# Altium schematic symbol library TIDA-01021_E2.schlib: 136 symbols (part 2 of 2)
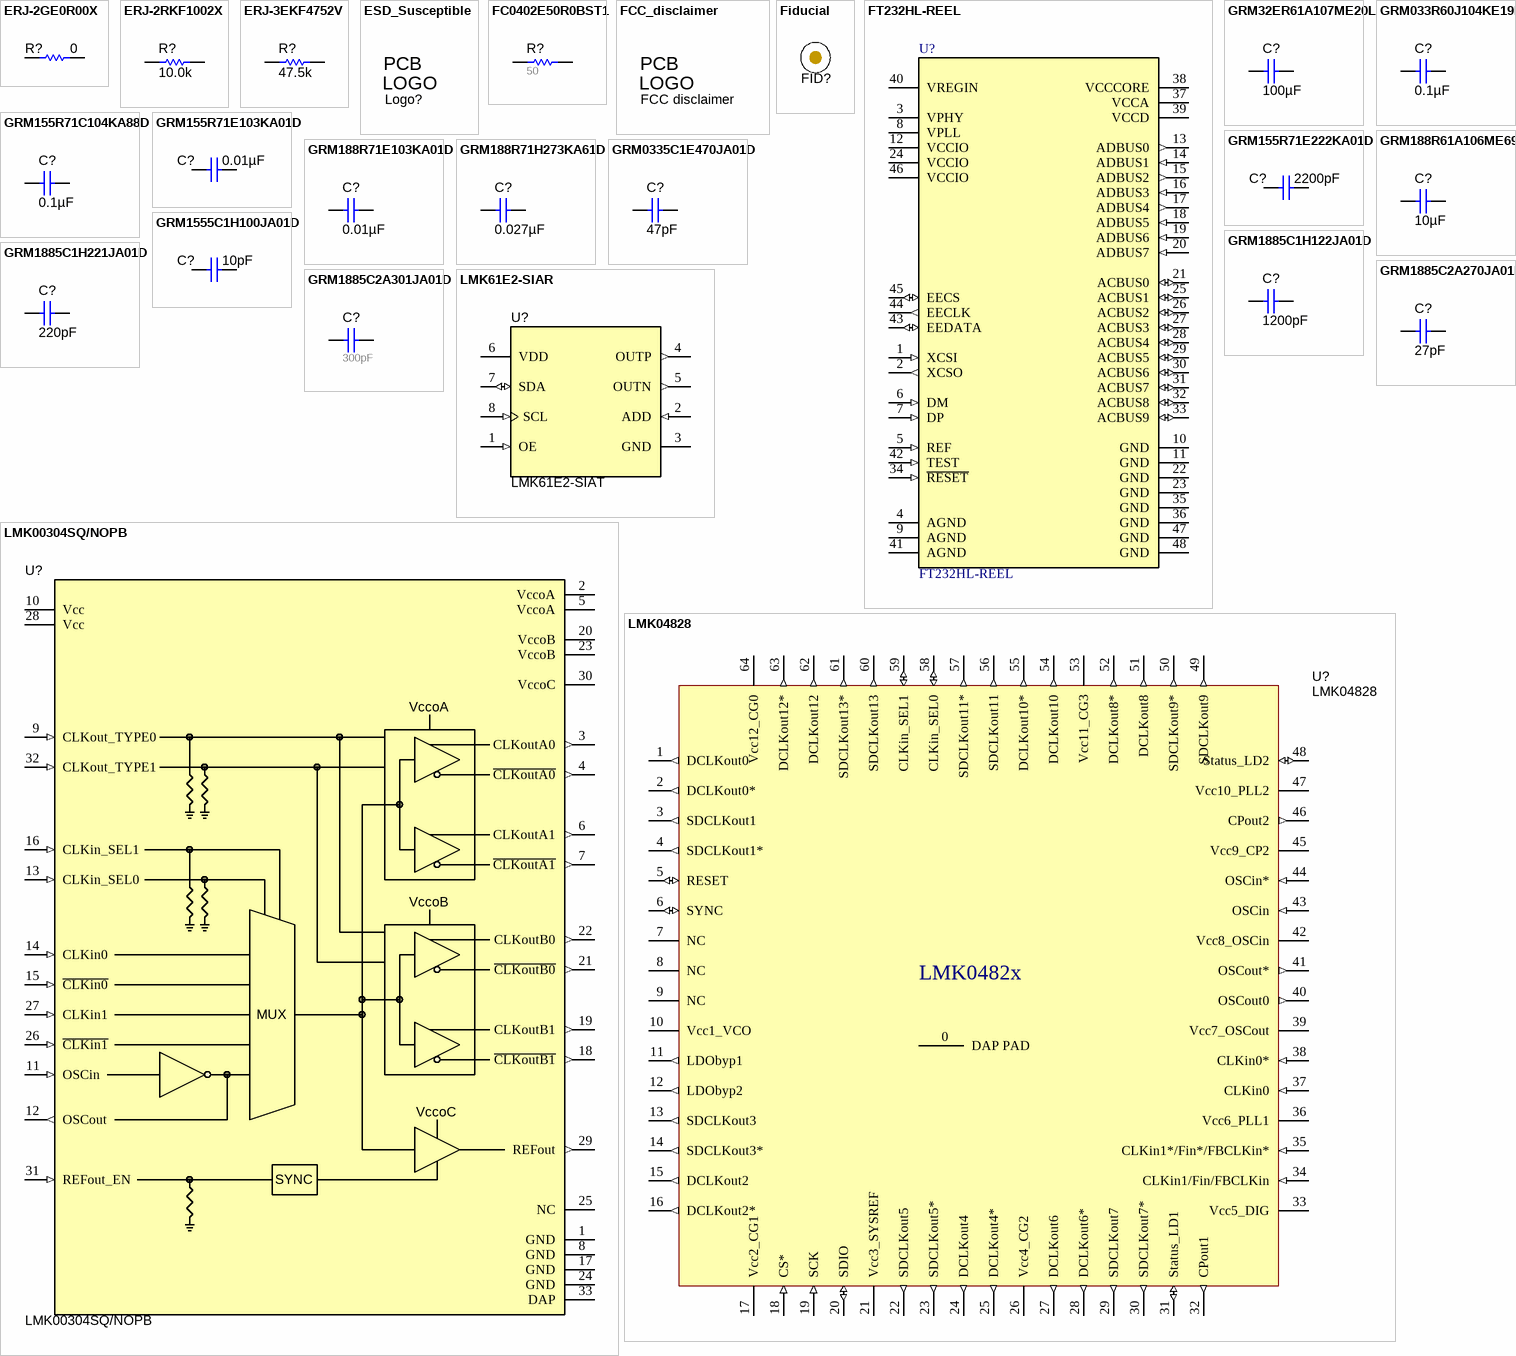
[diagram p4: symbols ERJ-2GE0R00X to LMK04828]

## LMK04828
designator U?
Manufacturer: Texas Instruments; PartNumber: LMK04828BISQ
footprint LLP64(NS_SQA64A)_HYBRID
footprint NKD0064A (QFN, 64-Leads, Body 9x9mm, Pitch 0.5mm)
pins: 0 DAP PAD (power) "DAP", 1 DCLKout0 (out) "CG0", 2 DCLKout0* (out) "CG0", 3 SDCLKout1 (out) "CG0", 4 SDCLKout1* (out) "CG0", 5 RESET (io), 6 SYNC (io), 7 NC, 8 NC, 9 NC, 10 Vcc1_VCO (power) "VCC_VCO_LDO", 11 LDObyp1 (out), 12 LDObyp2 (out), 13 SDCLKout3 (out) "CG1", 14 SDCLKout3* (out) "CG1", 15 DCLKout2 (out) "CG1", 16 DCLKout2* (out) "CG1", 17 Vcc2_CG1 (power) "VCC_CG1", 18 CS* (in), 19 SCK (in) "CG2", 20 SDIO (io) "CG2", 21 Vcc3_SYSREF (power) "CG2", 22 SDCLKout5 (out) "CG2", 23 SDCLKout5* (out), 24 DCLKout4 (out) "VCC_Digital", 25 DCLKout4* (out), 26 Vcc4_CG2 (power), 27 DCLKout6 (out) "Status", 28 DCLKout6* (out), 29 SDCLKout7 (out), 30 SDCLKout7* (out), 31 Status_LD1 (io), 32 CPout1 (out), 33 Vcc5_DIG (power) "Status", 34 CLKin1/Fin/FBCLKin (in), 35 CLKin1*/Fin*/FBCLKin* (in) "VCC_CP1", 36 Vcc6_PLL1 (power), 37 CLKin0 (in), 38 CLKin0* (in) "VCC_OSCin", 39 Vcc7_OSCout (power), 40 OSCout0 (out), 41 OSCout* (out) "OSCout", 42 Vcc8_OSCin (power), 43 OSCin (in) "VCC_DIV", 44 OSCin* (in) "uWire", 45 Vcc9_CP2 (power) "Vcc_CP2", 46 CPout2 (out) "uWire", 47 Vcc10_PLL2 (power) "Vcc_PLL2", 48 Status_LD2 (io) "CG3", 49 SDCLKout9 (out) "CG3", 50 SDCLKout9* (out) "CG3", 51 DCLKout8 (out) "CG3", 52 DCLKout8* (out) "VCC_CG4", 53 Vcc11_CG3 (power) "CG4", 54 DCLKout10 (out) "CG4", 55 DCLKout10* (out) "CG4", 56 SDCLKout11 (out) "CG4", 57 SDCLKout11* (out) "VCC_CG5", 58 CLKin_SEL0 (io) "CG5", 59 CLKin_SEL1 (io) "CG5", 60 SDCLKout13 (out) "CG5", 61 SDCLKout13* (out) "CG5", 62 DCLKout12 (out) "Status", 63 DCLKout12* (out), 64 Vcc12_CG0 (power)

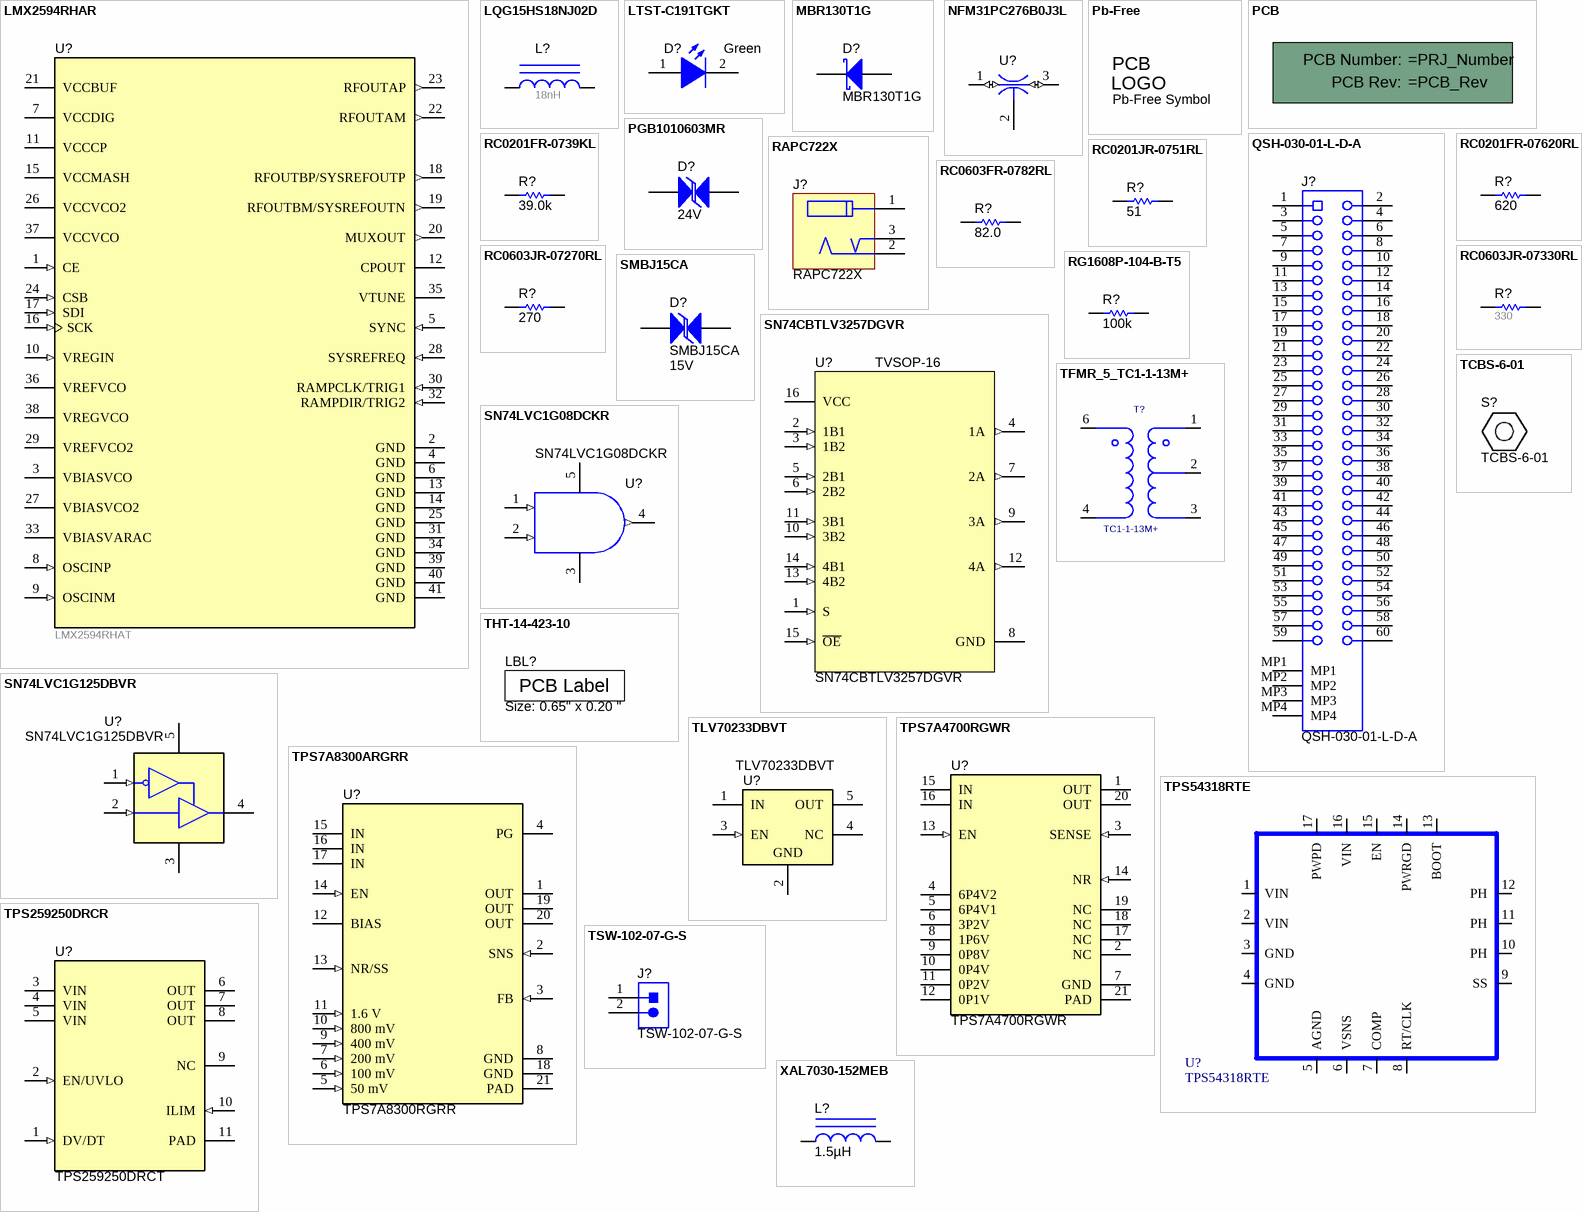
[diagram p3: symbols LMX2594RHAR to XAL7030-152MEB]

## LMX2594RHAR
designator U?, comment LMX2594RHAT
High Performance, Wideband PLLatinum RF Synthesizer, RHA0040A (VQFN-40); Manufacturer: Texas Instruments; SymbolCreator: Altium; SizeArea_mm2: 36; SizeAreaWB_mm2: 64; SizeX_mm: 6; SizeZ_mm: 1; CompType: IC; U/M: EA
footprint RHA0040A (QFN, 40-Leads, Body 6x6mm, Pitch 0.5mm, Thermal Pad 4.6x4.6mm, TI Recommended)
footprint RHA0040A_NV
footprint RHA0040C
pins: 1 CE (in), 2 GND (power), 3 VBIASVCO, 4 GND (power), 5 SYNC (in), 6 GND (power), 7 VCCDIG (power), 8 OSCINP (in), 9 OSCINM (in), 10 VREGIN (in), 11 VCCCP (power), 12 CPOUT, 13 GND (power), 14 GND (power), 15 VCCMASH (power), 16 SCK (in), 17 SDI (in), 18 RFOUTBP/SYSREFOUTP (out), 19 RFOUTBM/SYSREFOUTN (out), 20 MUXOUT (out), 21 VCCBUF (power), 22 RFOUTAM (out), 23 RFOUTAP (out), 24 CSB (in), 25 GND (power), 26 VCCVCO2 (power), 27 VBIASVCO2, 28 SYSREFREQ (in), 29 VREFVCO2, 30 RAMPCLK/TRIG1 (in), 31 GND (power), 32 RAMPDIR/TRIG2 (in), 33 VBIASVARAC, 34 GND (power), 35 VTUNE, 36 VREFVCO, 37 VCCVCO (power), 38 VREGVCO, 39 GND (power), 40 GND (power), 41 GND (power)

## LQG15HS18NJ02D
designator L?  ValueDisplayed: 18nH  (hidden comment: LQG15HS18NJ02D)
Inductor, Multilayer, Air Core, 18 nH, 0.3 A, 0.36 ohm, SMD; Manufacturer: MuRata; Value: 18nH; Ind_H: 18.0E-9; Imax_A: 0.3; Irms: 0.3A @ C rise; Isat: 0.3A @ % inductance drop; DCR_ohm: 0.36; Value2: 0.3A; AEC Category: Q200
signal-integrity model Inductor
simulation model Inductor
footprint IND_LQG15H
pins: 1, 2

## LTST-C191TGKT
designator D?  value Green  (hidden comment: LTST-C191TGKT)
LED, Green, SMD; Manufacturer: Lite-On; Type: InGaN; Vf_V: 3.2; Value2: 3.2V; Io_A: 0.02; Value1: W; U/M: EA
signal-integrity model Diode
footprint LTST-C191_Green
pins: 1 A, 2 K

## MBR130T1G
designator D?
Diode, Schottky, 30 V, 1 A, SOD-123; Manufacturer: ON Semiconductor; U/M: EA; Vf_V: 0.47; Value: 30V; Value1: 1A; Value2: 0.47V; Io_A: 1; Vr_V: 30; TJmax_C: 125; RJC_CperW: 108; SizeAreaWB_mm2: 13.095; SizeArea_mm2: 6.545; SizeX_mm: 3.85; SizeY_mm: 1.7; SizeZ_mm: 1.35; AEC Category: Q101
signal-integrity model Diode
simulation model mbr130prl
footprint SOD-123
pins: 1 K, 2 A

## NFM31PC276B0J3L
designator U?  (value not drawn)
FILTER LC HIGH FREQ 27uF 1206; Manufacturer: MuRata; SymbolCreator: Altium
footprint Murata_NFM31P
pins: 1 (io), 2 (power), 3 (io)

## Pb-Free
designator Logo?, comment Pb-Free Symbol  (no BOM)
SymbolCreator: a0412235
footprint Pb-Free_Overlay_Medium
footprint Pb-Free_Overlay_Small

## PCB
designator !PCB?, comment Printed Circuit Board  (value not drawn)  (mechanical)
Manufacturer: Any; SymbolCreator: a0412235; CompType: PCB
1 alternate drawing of the same symbol

## PGB1010603MR
designator D?  value 24V  (hidden comment: PGB1010603MR)
PulseGuard ESD Suppressor, 24VDC, SMT; Manufacturer: Littelfuse
footprint PGB1_0603
pins: 1, 2

## QSH-030-01-L-D-A
designator J?
Receptacle, 0.5 mm, 30x2, Gold, TH; Manufacturer: Samtec; SymbolCreator: Altium; Pitch_mm: 0.5; Gender: Female; Shrouded: N; Row_Count: 2; RowSpacing_mm: 5.73
footprint Samtec_QSH-030-01-X-D-A
pins: 1, 2, 3, 4, 5, 6, 7, 8, 9, 10, 11, 12, 13, 14, 15, 16, 17, 18, 19, 20, 21, 22, 23, 24, 25, 26, 27, 28, 29, 30, 31, 32, 33, 34, 35, 36, 37, 38, 39, 40, 41, 42, 43, 44, 45, 46, 47, 48, 49, 50, 51, 52, 53, 54, 55, 56, 57, 58, 59, 60, MP1, MP2, MP3, MP4

## RAPC722X
designator J?
Power Jack, mini, 2.1mm OD, R/A, TH; Manufacturer: Switchcraft; SymbolCreator: a0799628
footprint CONN_RAPC722X
pins: 1, 2, 3

## RC0201FR-0739KL
designator R?  ValueDisplayed: 39.0k  (hidden comment: RC0201FR-0739KL)
RES, 39.0 k, 1%, 0.05 W, 0201; Manufacturer: Yageo America; CompType: Resistor; Value: 39.0k; Res_ohm: 39000; Value_Code: 39k0; Tolerance_%: 1; Power_W: 0.05; Value2: 0.05W; VDC_V: 25; TempCo: 200 ppm/C; SizeArea_mm2: 0.18; SizeX_mm: 0.6; SizeY_mm: 0.3; SizeZ_mm: 0.26; U/M: EA; AEC Category: Q200; AEC Qualified: N
signal-integrity model Resistor
simulation model Resistor
footprint 0201
footprint 0201M
footprint 0201L
footprint 0201_Silk
pins: 1, 2

## RC0201FR-07620RL
designator R?  ValueDisplayed: 620  (hidden comment: RC0201FR-07620RL)
RES, 620, 1%, 0.05 W, 0201; Manufacturer: Yageo America; CompType: Resistor; Value: 620; Value_Code: 620R; Tolerance_%: 1; Power_W: 0.05; Value2: 0.05W; VDC_V: 25; TempCo: 200 ppm/C; SizeArea_mm2: 0.18; SizeX_mm: 0.6; SizeY_mm: 0.3; SizeZ_mm: 0.26; U/M: EA; AEC Category: Q200; AEC Qualified: N
signal-integrity model Resistor
simulation model Resistor
footprint 0201
footprint 0201M
footprint 0201L
footprint 0201_Silk
pins: 1, 2

## RC0201JR-0751RL
designator R?  ValueDisplayed: 51  (hidden comment: RC0201JR-0751RL)
RES, 51, 5%, 0.05 W, 0201; Manufacturer: Yageo America; CompType: Resistor; Value: 51; Value_Code: 51R0; Tolerance_%: 5; Power_W: 0.05; Value2: 0.05W; VDC_V: 25; TempCo: 200 ppm/C; SizeArea_mm2: 0.18; SizeX_mm: 0.6; SizeY_mm: 0.3; SizeZ_mm: 0.26; EIA_Code: E24; U/M: EA; AEC Category: Q200; AEC Qualified: N
signal-integrity model Resistor
simulation model Resistor
footprint 0201
footprint 0201M
footprint 0201L
footprint 0201_Silk
pins: 1, 2

## RC0603FR-0782RL
designator R?  ValueDisplayed: 82.0  (hidden comment: RC0603FR-0782RL)
RES, 82.0, 1%, 0.1 W, 0603; Manufacturer: Yageo America; CompType: Resistor; Value: 82.0; Res_ohm: 82; Value_Code: 82R0; Tolerance_%: 1; Power_W: 0.1; Value2: 0.1W; VDC_V: 150; TempCo: 200 ppm/C; SizeArea_mm2: 1.28; SizeX_mm: 1.6; SizeY_mm: 0.8; U/M: EA; AEC Category: Q200
signal-integrity model Resistor
simulation model Resistor
footprint 0603
footprint 0603M
footprint 0603L
footprint 0603_HV
footprint 0603S
pins: 1, 2

## RC0603JR-07270RL
designator R?  ValueDisplayed: 270  (hidden comment: RC0603JR-07270RL)
RES, 270, 5%, 0.1 W, 0603; Manufacturer: Yageo America; CompType: Resistor; Tolerance_%: 5; VDC_V: 50; Power_W: 0.1; Value: 270; U/M: EA; Value_Code: 270R; Value2: 0.1W; TempCo: 100 ppm/C; EIA_Code: E24; SizeArea_mm2: 1.28; SizeX_mm: 1.6; SizeY_mm: 0.8; SizeZ_mm: 1; AEC Category: Q200
signal-integrity model Resistor
simulation model Resistor
footprint 0603
footprint 0603M
footprint 0603L
footprint 0603_HV
footprint 0603S
pins: 1, 2

## RC0603JR-07330RL
designator R?  value 330  (hidden comment: RC0603JR-07330RL)
RES, 330 ohm, 5%, 0.1W, 0603; Manufacturer: Yageo America; CompType: Resistor; Tolerance_%: 5; VDC_V: 50; Power_W: 0.1; U/M: EA; Value_Code: 330R; EIA_Code: E24
signal-integrity model Resistor
simulation model Resistor
footprint 0603
footprint 0603M
footprint 0603L
footprint 0603_HV
pins: 1, 2

## RG1608P-104-B-T5
designator R?  ValueDisplayed: 100k  (hidden comment: RG1608P-104-B-T5)
RES, 100 k, 0.1%, 0.1 W, 0603; Manufacturer: Susumu Co Ltd; CompType: Resistor; Value: 100k; Res_ohm: 100000; Tolerance_%: 0.1; Value2: 0.1W; VDC_V: 75; TempCo: 25 ppm/C; SizeArea_mm2: 1.28; SizeX_mm: 1.6; SizeY_mm: 0.8; SizeZ_mm: 1; EIA_Code: E192; U/M: EA; AEC Category: Q200
signal-integrity model Resistor
simulation model Resistor
footprint 0603
footprint 0603M
footprint 0603L
footprint 0603_HV
footprint 0603S
pins: 1, 2

## SMBJ15CA
designator D?  value 15V
Diode, TVS, Bi, 15 V, 24.4 Vc, SMB; Manufacturer: Fairchild Semiconductor; U/M: EA; Vr_V: 15; Value1: W; AEC Category: Q101
footprint SMB-Bi
pins: 1, 2

## SN74CBTLV3257DGVR
designator U?  PackageDescription: TVSOP-16
Low-Voltage 4-Bit 1-Of-2 FET Multiplexer/Demultiplexer, DGV0016A (TVSOP-16); Manufacturer: Texas Instruments; SymbolCreator: Altium; SizeArea_mm2: 40.96; SizeAreaWB_mm2: 70.56; SizeX_mm: 6.4; SizeZ_mm: 1.2; CompType: IC; U/M: EA
footprint DGV0016A_N
footprint DGV0016A_M
footprint DGV0016A_L
pins: 1 S (in), 2 1B1 (in), 3 1B2 (in), 4 1A (out), 5 2B1 (in), 6 2B2 (in), 7 2A (out), 8 GND (power), 9 3A (out), 10 3B2 (in), 11 3B1 (in), 12 4A (out), 13 4B2 (in), 14 4B1 (in), 15 ~{OE} (in), 16 VCC (power)

## SN74LVC1G08DCKR
designator U?
Single 2-Input Positive-AND Gate, DCK0005A (SOT-5); Alternate PartNumber: SN74LVC1G08DCKT; Manufacturer: Texas Instruments; CompType: IC; SizeArea_mm2: 4.2; SizeAreaWB_mm2: 9.3; SizeX_mm: 2.1; SizeY_mm: 2; SizeZ_mm: 1.1; U/M: EA
footprint DCK0005A_N
footprint DCK0005A_M
footprint DCK0005A_L
pins: 1 A (in), 2 B (in), 3 V- (power), 4 Y (out), 5 V+ (power)

## SN74LVC1G125DBVR
designator U?
Single Bus Buffer Gate With 3-State Outputs, DBV0005A (SOT-5); Alternate PartNumber: SN74LVC1G125DBVT; Manufacturer: Texas Instruments; SymbolCreator: Altium; SizeArea_mm2: 8.12; SizeAreaWB_mm2: 14.82; SizeX_mm: 2.8; SizeY_mm: 2.9; SizeZ_mm: 1.45; CompType: IC; U/M: EA
footprint DBV0005A_N
footprint DBV0005A_M
footprint DBV0005A_L
pins: 1 ~{OE} (in), 2 A (in), 3 GND (power), 4 Y (hiz), 5 VCC (power)

## TCBS-6-01
designator S?
HEX STANDOFF SPACER, 9.53 mm; Manufacturer: Richco Plastics; SymbolCreator: a0412235
footprint TCBS-6-01

## TFMR_5_TC1-1-13M+
designator T?, comment TC1-1-13M+
Mfr_Name: Mini-Circuits; Mfr-_Part_Number: TC1-1-13MA+
footprint TFMR_5_150x150_50
footprint TFMR_5_150x150_50
pins: 1 secondary_dot, 2 secondary_ct, 3 secondary, 4 primary, 6 primary_dot

## THT-14-423-10
designator LBL?, comment Size: 0.65" x 0.20 "
Thermal Transfer Printable Labels, 0.650" W x 0.200" H - 10,000 per roll; Manufacturer: Brady; PartNumber: THT-14-423-10; SymbolCreator: a0412235; CompType: Label
footprint Label_650x200

## TLV70233DBVT
designator U?
Single Output LDO, 300 mA, Fixed 3.3 V Output, 2 to 5.5 V Input, with Low IQ, 5-pin SOT-23 (DBV), -40 to 125 degC, Green (RoHS & no Sb/Br); Manufacturer: Texas Instruments; Alternate PartNumber: Equivalent; Accuracy(%): 2; Fixed Output Options(V): 3.3; Iout(Max)(A): 0.3; Iq(Typ)(mA): 0.03; SubFamily: Single Channel LDO; Vdo(Typ)(mV): 220; Vin(Max)(V): 5.5
footprint DBV0005A_N (SOT23, 5-Leads, Body 2.9x1.6mm, Pitch 0.95mm, IPC Medium Density)
footprint DBV0005A_L (SOT23, 5-Leads, Body 2.9x1.6mm, Pitch 0.95mm, IPC High Density)
footprint DBV0005A_M (SOT23, 5-Leads, Body 2.9x1.6mm, Pitch 0.95mm, IPC Low Density)
pins: 1 IN (power) "Input supply voltage", 2 GND (power) "Ground", 3 EN (in) "Enable input", 4 NC "No connected", 5 OUT (power) "Regulated output voltage"

## TPS7A4700RGWR
designator U?
36-V, 1-A, 4.17-μVRMS, RF LDO Voltage Regulator, RGW0020A (VQFN-20); Alternate PartNumber: TPS7A4700RGWT; Manufacturer: Texas Instruments; SymbolCreator: a0412235; SizeArea_mm2: 25; SizeAreaWB_mm2: 49; SizeX_mm: 5; SizeZ_mm: 1; CompType: IC; U/M: EA
footprint RGW0020A
pins: 1 OUT (power), 2 NC, 3 SENSE (in), 4 6P4V2, 5 6P4V1, 6 3P2V, 7 GND (power), 8 1P6V, 9 0P8V, 10 0P4V, 11 0P2V, 12 0P1V, 13 EN (in), 14 NR (in), 15 IN (power), 16 IN (power), 17 NC, 18 NC, 19 NC, 20 OUT (power), 21 PAD

## TPS7A8300ARGRR
designator U?, comment TPS7A8300RGRR
2-A, 6-uVRMS, RF, LDO Voltage Regulator, RGR0020A (VQFN-20); Manufacturer: Texas Instruments; SymbolCreator: a0411947; SizeArea_mm2: 12.25; SizeAreaWB_mm2: 20.25; SizeX_mm: 3.5; SizeZ_mm: 1; CompType: IC; U/M: EA
footprint RGR0020A
footprint RGR0020A_NV
pins: 1 OUT (power), 2 SNS (in), 3 FB (in), 4 PG (oc), 5 50 mV (in), 6 100 mV (in), 7 200 mV (in), 8 GND (power), 9 400 mV (in), 10 800 mV (in), 11 1.6 V (in), 12 BIAS (power), 13 NR/SS (in), 14 EN (in), 15 IN (power), 16 IN (power), 17 IN (power), 18 GND (power), 19 OUT (power), 20 OUT (power), 21 PAD (power)

## TPS54318RTE
designator U?
IC, 2.95V To 6V Input, 3A Output, 2MHz, Synchronous SWIFT; Manufacturer: TI; Alternate Manufacturer: None; Area: 33865
footprint RTE-16
pins: 1 VIN, 2 VIN, 3 GND, 4 GND, 5 AGND, 6 VSNS, 7 COMP, 8 RT/CLK, 9 SS, 10 PH, 11 PH, 12 PH, 13 BOOT, 14 PWRGD, 15 EN, 16 VIN, 17 PWPD
1 alternate drawing of the same symbol

## TPS259250DRCR
designator U?, comment TPS259250DRCT
5V, 5A, 30mΩ eFuse with Adjustable +/-15% Accurate Current Limit, DRC0010J (VSON-10); Manufacturer: Texas Instruments; SymbolCreator: Altium; SizeArea_mm2: 9; SizeAreaWB_mm2: 16; SizeX_mm: 3; SizeZ_mm: 1; CompType: IC; U/M: EA
footprint DRC0010J
footprint DRC0010J_NV
pins: 1 DV/DT (in) "dV/dT", 2 EN/UVLO (in), 3 VIN (power), 4 VIN (power), 5 VIN (power), 6 OUT (power), 7 OUT (power), 8 OUT (power), 9 NC "BFET", 10 ILIM (in), 11 PAD (power)

## TSW-102-07-G-S
designator J?
Header, 100mil, 2x1, Gold, TH; Manufacturer: Samtec; SymbolCreator: a0412235; Pitch_mm: 2.54; Gender: Male; Shrouded: N; Row_Count: 1; Current_A: 6.3; Voltage_V: 550; Cert_CSA: Y
footprint TSW-102-07-G-S
footprint TSW-102-07-X-S
pins: 1, 2
1 alternate drawing of the same symbol

## XAL7030-152MEB
designator L?  ValueDisplayed: 1.5µH  (hidden comment: XAL7030-152MEB)
Inductor, Shielded, Composite, 1.5 µH, 15 A, 0.0076 ohm, SMD; Manufacturer: Coilcraft; Value: 1.5uH; Ind_H: 1.5E-6; Imax_A: 15; Irms: 15A @ 40C rise; Isat: 23.5A @ 0.7% inductance drop; DCR_ohm: 0.0076; Value2: 15A; SizeAreaWB_mm2: 100; SizeArea_mm2: 64; SizeX_mm: 8; SizeZ_mm: 3.1; AEC Category: Q200
signal-integrity model Inductor
simulation model Inductor
footprint XAL7030 (Coilcraft XAL7030 7.5 x.7.5 x 3.1 mm)
pins: 1, 2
